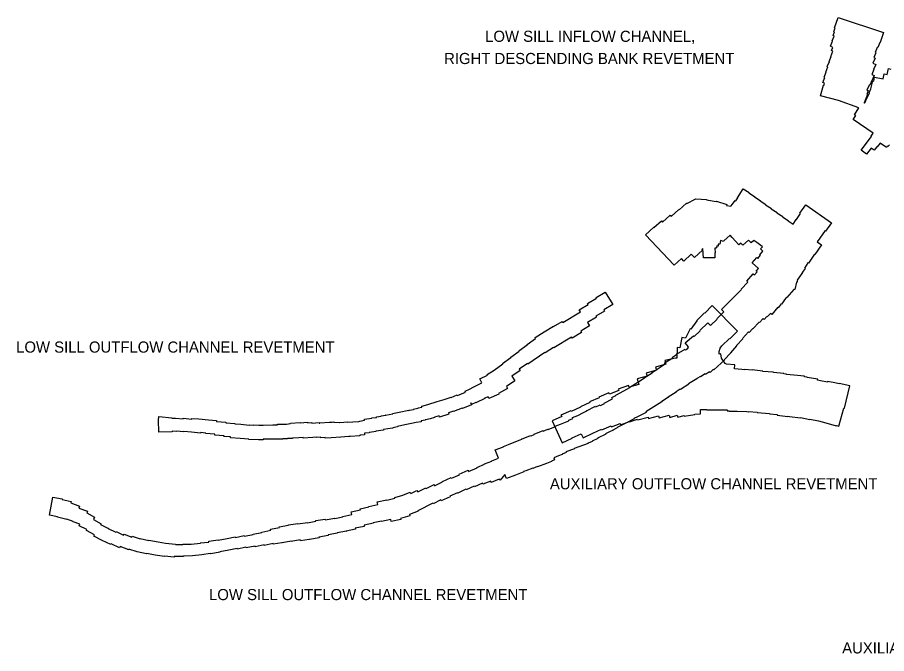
# Model space of a CAD drawing. Extents: x 2650582 to 3923188, y 277893 to 989177.
# Drawn here: x 3186396 to 3198891, y 930026 to 939166 of the extents above; entities that cross this region are included whole.
import ezdxf

# ---------------------------------------------------------------- set-up
doc = ezdxf.new("R2010")
doc.units = 0
doc.layers.add('Level 3', color=7, linetype='Continuous')

msp = doc.modelspace()

# ---------------------------------------------------------------- linework, layer by layer
at = {"layer": 'Level 3'}
for points in [[(3197941, 938040), (3197982, 938191), (3197989, 938189), (3198000, 938220), (3197972, 938232), (3198004, 938302), (3197994, 938306), (3198024, 938378), (3198017, 938381), (3198048, 938454), (3198038, 938459), (3198068, 938531), (3198065, 938532), (3198096, 938603), (3198088, 938606), (3198119, 938679), (3198098, 938690), (3198119, 938736), (3198083, 938752), (3198113, 938827), (3198106, 938830), (3198135, 938899), (3198122, 938905), (3198143, 938958), (3198133, 938962), (3198151, 939013), (3198143, 939016), (3198194, 939166), (3198848, 938951)], [(3198848, 938951), (3198799, 938806), (3198792, 938808), (3198763, 938733), (3198757, 938735), (3198726, 938663), (3198735, 938659), (3198707, 938590), (3198727, 938581), (3198695, 938508), (3198735, 938490), (3198704, 938420), (3198709, 938418), (3198678, 938348), (3198711, 938333), (3198648, 938191), (3198640, 938194), (3198607, 938123), (3198627, 938114), (3198606, 938060), (3198614, 938057), (3198566, 937938)], [(3198566, 937938), (3198574, 937933), (3198591, 937963), (3198587, 937965), (3198644, 938083), (3198642, 938084), (3198663, 938138), (3198691, 938254), (3198707, 938251), (3198719, 938307), (3198842, 938285), (3198856, 938355), (3198900, 938347), (3198918, 938430), (3198951, 938424)], [(3198410, 937700), (3198447, 937756), (3198428, 937768), (3198491, 937867), (3198201, 937972), (3197941, 938040)], [(3198525, 937257), (3198676, 937456), (3198669, 937461), (3198696, 937501), (3198410, 937700)], [(3198934, 937335), (3198907, 937311), (3198901, 937318), (3198889, 937299), (3198797, 937360), (3198757, 937305), (3198751, 937309), (3198714, 937257), (3198670, 937288), (3198603, 937199), (3198525, 937257)], [(3196678, 936485), (3196714, 936536), (3196725, 936529), (3196752, 936572), (3196746, 936576), (3196828, 936705), (3196914, 936650), (3196910, 936644), (3196993, 936591), (3196991, 936587), (3197074, 936534), (3197073, 936531), (3197156, 936478), (3197152, 936473), (3197235, 936420), (3197233, 936416), (3197316, 936363), (3197313, 936359), (3197397, 936306), (3197393, 936301), (3197476, 936248), (3197474, 936244), (3197547, 936196)], [(3195909, 936400), (3196013, 936495), (3196018, 936491), (3196148, 936560), (3196304, 936550), (3196304, 936545), (3196443, 936520), (3196446, 936527), (3196594, 936478), (3196589, 936463), (3196654, 936456), (3196678, 936485)], [(3196250, 935845), (3196235, 935831), (3196244, 935821), (3196131, 935715), (3196082, 935766), (3195975, 935666), (3195941, 935703), (3195836, 935607), (3195427, 936043), (3195544, 936151), (3195547, 936148), (3195653, 936244), (3195671, 936225), (3195781, 936324), (3195796, 936307), (3195903, 936406), (3195909, 936400)], [(3197547, 936196), (3197592, 936263), (3197595, 936262), (3197655, 936348), (3197644, 936355), (3197728, 936474), (3198098, 936216), (3198014, 936097), (3198006, 936103), (3197929, 935993), (3197929, 935994), (3197894, 935941), (3197955, 935899), (3197859, 935760), (3197854, 935763), (3197768, 935634), (3197758, 935640), (3197710, 935565), (3197719, 935559), (3197679, 935500), (3197680, 935499), (3197606, 935390), (3197608, 935389), (3197605, 935383), (3197604, 935364), (3197597, 935364), (3197574, 935255), (3197557, 935257), (3197456, 935143), (3197452, 935146)], [(3196982, 935962), (3196944, 935926), (3196905, 935968), (3196824, 935894), (3196797, 935924), (3196767, 935898), (3196673, 936006), (3196640, 936037), (3196553, 935954)], [(3196553, 935954), (3196550, 935958), (3196545, 935945), (3196502, 935960), (3196493, 935906), (3196471, 935909), (3196470, 935881), (3196452, 935882), (3196451, 935861), (3196442, 935861), (3196441, 935850), (3196423, 935851), (3196426, 935782), (3196423, 935782), (3196424, 935714), (3196257, 935712), (3196256, 935774), (3196254, 935774), (3196250, 935845)], [(3196959, 935638), (3197027, 935716), (3197041, 935704), (3197078, 935751), (3197070, 935757), (3197114, 935810), (3197080, 935839), (3197108, 935871), (3197104, 935874), (3197104, 935875), (3197024, 935931), (3197025, 935932), (3196982, 935962)], [(3196044, 934432), (3195996, 934489), (3196116, 934590), (3196123, 934583), (3196211, 934662), (3196207, 934667), (3196319, 934777), (3196357, 934739), (3196454, 934831), (3196449, 934836), (3196551, 934936), (3196519, 934970), (3196619, 935068), (3196805, 935259), (3196802, 935261), (3196894, 935363), (3196880, 935376), (3196972, 935483), (3196992, 935466), (3197030, 935511), (3197018, 935521), (3197051, 935559), (3196959, 935638)], [(3193844, 934554), (3193837, 934565), (3193967, 934649), (3193966, 934650), (3194101, 934729), (3194104, 934724), (3194229, 934795), (3194236, 934785), (3194491, 934935), (3194473, 934964), (3194601, 935041), (3194593, 935055), (3194719, 935131), (3194714, 935140), (3194846, 935220), (3194955, 935042), (3194827, 934966), (3194838, 934947), (3194711, 934874), (3194720, 934858), (3194593, 934781), (3194621, 934734), (3194494, 934657), (3194504, 934640), (3194371, 934559), (3194363, 934572), (3194105, 934420), (3194103, 934423), (3193982, 934345), (3193977, 934353), (3193733, 934185)], [(3197452, 935146), (3197436, 935129), (3197381, 935047), (3197374, 935052), (3197333, 934996), (3197325, 935002), (3197286, 934949), (3197282, 934952), (3197241, 934897), (3197220, 934913), (3197175, 934864), (3197169, 934870), (3197129, 934827), (3197118, 934838), (3197066, 934782), (3197059, 934789), (3196966, 934691), (3196963, 934694), (3196913, 934641), (3196906, 934647), (3196819, 934554), (3196823, 934550), (3196731, 934453), (3196735, 934449), (3196703, 934416), (3196706, 934413), (3196647, 934349), (3196651, 934345), (3196558, 934246), (3196561, 934243), (3196512, 934199), (3196514, 934197), (3196406, 934101), (3196400, 934108), (3196353, 934066), (3196345, 934075), (3196287, 934035), (3196281, 934043)], [(3196703, 934115), (3196708, 934173), (3196591, 934183), (3196570, 934196), (3196518, 934272), (3196506, 934334), (3196485, 934330), (3196486, 934365), (3196496, 934415), (3196522, 934449), (3196524, 934447), (3196633, 934552), (3196637, 934548), (3196747, 934660), (3196384, 935025), (3196278, 934918), (3196275, 934921), (3196162, 934810), (3196164, 934807), (3196076, 934686), (3196068, 934690), (3195999, 934556), (3195948, 934566), (3195918, 934421), (3195880, 934422), (3195874, 934272), (3195855, 934270), (3195854, 934272), (3195702, 934239), (3195715, 934182), (3195569, 934140), (3195582, 934098), (3195436, 934055), (3195449, 934013), (3195307, 933972), (3195329, 933891), (3195191, 933853), (3195182, 933879), (3195033, 933827), (3195041, 933805), (3194907, 933755), (3194898, 933773), (3194753, 933712), (3194758, 933701), (3194622, 933641), (3194625, 933635), (3194489, 933572), (3194491, 933568), (3194358, 933506), (3194353, 933516), (3194210, 933452), (3194221, 933430), (3194085, 933368)], [(3193073, 933914), (3193045, 933975), (3193155, 934025), (3193147, 934037), (3193251, 934100), (3193375, 934187), (3193369, 934195), (3193490, 934280), (3193487, 934284), (3193610, 934369), (3193604, 934378), (3193725, 934464), (3193722, 934468), (3193844, 934554)], [(3195871, 934326), (3195994, 934399), (3195998, 934391), (3196040, 934416), (3196034, 934423), (3196044, 934432)], [(3194998, 933740), (3195115, 933801), (3195114, 933803), (3195202, 933848), (3195200, 933852), (3195314, 933924), (3195313, 933925), (3195410, 933987), (3195408, 933990), (3195523, 934062), (3195521, 934065), (3195595, 934111), (3195593, 934114), (3195708, 934187), (3195699, 934203), (3195819, 934274), (3195811, 934287), (3195873, 934323), (3195871, 934326)], [(3193733, 934185), (3193727, 934194), (3193611, 934114), (3193623, 934094), (3193502, 934010), (3193545, 933946), (3193426, 933863), (3193440, 933837), (3193312, 933765), (3193317, 933754), (3193175, 933689), (3193162, 933717)], [(3196281, 934043), (3196216, 934004), (3196214, 934007), (3196162, 933977), (3196164, 933974), (3196045, 933903), (3196049, 933895), (3195926, 933822), (3195925, 933824), (3195866, 933786), (3195868, 933783), (3195753, 933710), (3195755, 933708), (3195658, 933647), (3195660, 933644), (3195546, 933572), (3195547, 933570), (3195432, 933498), (3195435, 933492), (3195308, 933427), (3195308, 933427), (3195259, 933402), (3195261, 933398)], [(3197114, 934084), (3196959, 934101), (3196958, 934096), (3196847, 934106), (3196847, 934104), (3196808, 934107), (3196808, 934106), (3196703, 934115)], [(3198360, 933871), (3198208, 933905), (3198208, 933904), (3198191, 933908), (3198191, 933906), (3198121, 933920), (3198043, 933937), (3198040, 933927), (3197940, 933946), (3197940, 933945), (3197899, 933953), (3197901, 933970), (3197750, 933993), (3197750, 933999), (3197712, 934003), (3197713, 934010), (3197558, 934028), (3197558, 934025), (3197450, 934036), (3197450, 934041), (3197413, 934044), (3197413, 934049), (3197263, 934063), (3197263, 934067), (3197114, 934081), (3197114, 934084)], [(3192296, 933603), (3192296, 933606), (3192429, 933649), (3192430, 933646), (3192531, 933678), (3192531, 933676), (3192633, 933709), (3192633, 933707), (3192720, 933742), (3192722, 933736), (3192839, 933783), (3192833, 933795), (3192896, 933825), (3192895, 933827), (3192959, 933857), (3192958, 933860), (3193073, 933914)], [(3198274, 933554), (3198286, 933551), (3198360, 933871)], [(3193162, 933717), (3193112, 933694), (3193114, 933690), (3192986, 933630), (3192985, 933633), (3192924, 933603), (3192912, 933629), (3192924, 933601), (3192794, 933548), (3192791, 933554), (3192665, 933503), (3192663, 933508), (3192592, 933485), (3192599, 933465), (3192465, 933422), (3192459, 933443), (3192392, 933422), (3192394, 933417), (3192329, 933401), (3192330, 933398), (3192261, 933385), (3192259, 933384), (3192260, 933380), (3192198, 933368), (3192200, 933358), (3192129, 933347), (3192130, 933344), (3192061, 933334), (3192062, 933331), (3191965, 933312), (3191965, 933312), (3191859, 933291), (3191860, 933283), (3191791, 933271), (3191791, 933267), (3191722, 933257), (3191723, 933253), (3191658, 933244), (3191659, 933237)], [(3193311, 932834), (3193265, 932952), (3193385, 932998), (3193384, 932999), (3193458, 933028), (3193457, 933032), (3193587, 933083), (3193587, 933082), (3193623, 933096), (3193645, 933105), (3193644, 933107), (3193773, 933157), (3193775, 933152), (3193783, 933155), (3193783, 933156), (3193825, 933172), (3193823, 933178), (3193952, 933229), (3193954, 933224), (3194023, 933251), (3194025, 933246), (3194130, 933287), (3194128, 933292), (3194204, 933320), (3194202, 933324), (3194325, 933370), (3194321, 933380), (3194382, 933403), (3194376, 933417), (3194454, 933447), (3194534, 933488), (3194532, 933490), (3194580, 933514), (3194579, 933516), (3194705, 933581), (3194712, 933569), (3194771, 933599), (3194776, 933589), (3194835, 933619), (3194833, 933623), (3194952, 933685), (3194941, 933706), (3195000, 933736), (3194998, 933740)], [(3191624, 933441), (3191690, 933450), (3191689, 933452), (3191791, 933469), (3191790, 933477), (3191886, 933496), (3192024, 933523), (3192025, 933520), (3192033, 933521), (3192033, 933525), (3192088, 933533), (3192087, 933540), (3192158, 933553), (3192157, 933558), (3192212, 933568), (3192209, 933582), (3192296, 933603)], [(3194085, 933368), (3194228, 933056), (3194371, 933123), (3194370, 933125), (3194501, 933185), (3194529, 933126), (3194670, 933191), (3194668, 933195), (3194794, 933252), (3194799, 933240), (3194930, 933296), (3194935, 933282), (3195060, 933331), (3195068, 933312), (3195193, 933359), (3195195, 933355), (3195311, 933395), (3195315, 933383), (3195461, 933423), (3195466, 933403), (3195611, 933442), (3195620, 933411), (3195765, 933453), (3195775, 933420), (3195882, 933450), (3195888, 933425), (3195979, 933445), (3195980, 933439), (3196134, 933462), (3196134, 933465), (3196218, 933471), (3196214, 933532)], [(3196214, 933532), (3196307, 933532), (3196307, 933529), (3196334, 933529), (3196334, 933526), (3196483, 933528), (3196484, 933526), (3196598, 933526), (3196598, 933515), (3196627, 933514), (3196627, 933509), (3196741, 933508), (3196741, 933508), (3196882, 933502), (3196882, 933503), (3196910, 933501), (3196910, 933505), (3197028, 933496)], [(3197028, 933496), (3197028, 933489), (3197206, 933474), (3197206, 933472), (3197316, 933460), (3197316, 933453), (3197471, 933434), (3197471, 933438), (3197497, 933434), (3197651, 933412), (3197651, 933416), (3197788, 933391), (3197788, 933395), (3197910, 933369), (3198017, 933342), (3198016, 933340), (3198167, 933298), (3198169, 933304), (3198202, 933295), (3198274, 933554)], [(3190210, 933108), (3190073, 933107), (3190073, 933106), (3190004, 933105), (3190004, 933105), (3189930, 933105), (3189929, 933095), (3189862, 933097), (3189862, 933096), (3189721, 933101), (3189721, 933105), (3189598, 933116), (3189598, 933115), (3189459, 933128), (3189460, 933138), (3189366, 933146), (3189367, 933153), (3189235, 933164), (3189236, 933178), (3189102, 933189), (3189103, 933195), (3189028, 933201), (3189028, 933195), (3188900, 933206), (3188900, 933205), (3188791, 933215), (3188791, 933213), (3188685, 933223), (3188685, 933217), (3188623, 933220), (3188623, 933210), (3188427, 933205), (3188423, 933379), (3188426, 933379), (3188431, 933434), (3188617, 933415), (3188616, 933410), (3188668, 933408), (3188668, 933409), (3188777, 933400), (3188777, 933407), (3188905, 933396), (3188905, 933405), (3189002, 933397), (3189002, 933399), (3189141, 933386), (3189141, 933383), (3189259, 933373), (3189258, 933362), (3189392, 933350), (3189391, 933343), (3189523, 933332), (3189522, 933327), (3189607, 933320), (3189607, 933320), (3189728, 933309), (3189728, 933311), (3189796, 933309), (3189796, 933311), (3189865, 933308), (3189931, 933308), (3189931, 933310), (3190069, 933311), (3190069, 933315), (3190137, 933315)], [(3190137, 933315), (3190137, 933320), (3190264, 933321), (3190321, 933332), (3190321, 933337), (3190461, 933348), (3190462, 933343), (3190565, 933351), (3190565, 933342), (3190628, 933347), (3190629, 933336), (3190732, 933344), (3190733, 933337), (3190743, 933338), (3190743, 933340), (3190884, 933351), (3190884, 933349), (3190919, 933351), (3190946, 933354), (3190946, 933350), (3191025, 933346), (3191031, 933346), (3191031, 933346), (3191144, 933354), (3191144, 933352), (3191219, 933358), (3191219, 933356), (3191303, 933362), (3191303, 933362), (3191317, 933363), (3191386, 933382), (3191385, 933392), (3191493, 933407), (3191492, 933411), (3191557, 933420), (3191556, 933427), (3191625, 933436), (3191624, 933441)], [(3195261, 933398), (3195134, 933332), (3195133, 933334), (3195017, 933274), (3195019, 933270), (3194957, 933238), (3194958, 933237), (3194898, 933207), (3194899, 933206), (3194852, 933182), (3194853, 933180), (3194737, 933120), (3194738, 933118), (3194658, 933077), (3194659, 933073), (3194626, 933060), (3194611, 933053), (3194611, 933054), (3194598, 933050), (3194600, 933045), (3194467, 932995), (3194466, 932998), (3194401, 932973), (3194403, 932970), (3194281, 932923), (3194284, 932915), (3194227, 932892), (3194229, 932888), (3194173, 932866), (3194174, 932865), (3194105, 932838), (3194116, 932809), (3194073, 932793)], [(3191659, 933237), (3191551, 933222), (3191552, 933218), (3191452, 933204), (3191453, 933197), (3191384, 933192), (3191386, 933167), (3191318, 933162), (3191319, 933155), (3191179, 933144), (3191178, 933146), (3191160, 933145), (3191160, 933144), (3191047, 933136), (3191047, 933135), (3190906, 933124), (3190906, 933128), (3190822, 933122), (3190821, 933133), (3190759, 933128), (3190759, 933134), (3190691, 933129), (3190691, 933137), (3190644, 933133), (3190644, 933133), (3190504, 933122), (3190503, 933131), (3190441, 933126), (3190441, 933128), (3190350, 933121), (3190350, 933114), (3190278, 933114), (3190278, 933111), (3190210, 933111), (3190210, 933108)], [(3191824, 932258), (3191820, 932269), (3191937, 932301), (3192044, 932343), (3192052, 932324), (3192138, 932368), (3192150, 932348), (3192266, 932409), (3192272, 932398), (3192386, 932454), (3192394, 932438), (3192506, 932494), (3192505, 932497), (3192632, 932555), (3192637, 932544), (3192752, 932595), (3192748, 932603), (3192874, 932660), (3192881, 932644), (3193004, 932695), (3193001, 932702), (3193113, 932746), (3193111, 932752), (3193215, 932792), (3193214, 932796), (3193311, 932834)], [(3194073, 932793), (3194076, 932787), (3194003, 932758), (3194003, 932757), (3193874, 932707), (3193872, 932712), (3193807, 932687), (3193805, 932692), (3193704, 932653), (3193704, 932654), (3193673, 932642), (3193675, 932638), (3193556, 932591), (3193556, 932591), (3193426, 932540), (3193402, 932601)], [(3193402, 932601), (3193335, 932519), (3193321, 932530), (3193206, 932486), (3193200, 932503), (3193089, 932462), (3193084, 932473), (3192968, 932423), (3192963, 932433), (3192847, 932380), (3192843, 932388), (3192725, 932333), (3192723, 932335), (3192612, 932286), (3192615, 932278), (3192486, 932221), (3192481, 932234), (3192371, 932177), (3192367, 932187), (3192153, 932077), (3192155, 932073), (3192032, 932022), (3192036, 932005), (3191903, 931967), (3191906, 931952), (3191769, 931922)], [(3188509, 931420), (3188376, 931442), (3188376, 931442), (3188255, 931464), (3188254, 931458), (3188118, 931486), (3188119, 931488), (3188000, 931526), (3187996, 931517), (3187873, 931563), (3187864, 931545), (3187744, 931601), (3187741, 931594), (3187616, 931653), (3187496, 931714), (3187505, 931732), (3187389, 931793), (3187396, 931807), (3187285, 931861), (3187296, 931884), (3187196, 931919), (3187198, 931924), (3187108, 931959), (3187107, 931954), (3186972, 931984), (3186974, 931993), (3186857, 932014), (3186904, 932274), (3187042, 932248), (3187041, 932239), (3187167, 932210), (3187164, 932191), (3187288, 932142), (3187279, 932117), (3187402, 932073), (3187393, 932046), (3187506, 931988), (3187488, 931952), (3187598, 931892), (3187593, 931880), (3187704, 931825), (3187702, 931822), (3187811, 931771), (3187815, 931778), (3187923, 931729), (3187929, 931744), (3188042, 931700), (3188046, 931711), (3188159, 931677), (3188159, 931679), (3188285, 931653), (3188285, 931656), (3188418, 931632), (3188418, 931632), (3188526, 931614)], [(3190162, 931839), (3190160, 931849), (3190293, 931872), (3190292, 931875), (3190428, 931897), (3190429, 931891), (3190564, 931911), (3190564, 931907), (3190686, 931928), (3190685, 931936), (3190821, 931959), (3190823, 931947), (3190956, 931972), (3190957, 931967), (3191074, 931992), (3191073, 931998), (3191205, 932024), (3191196, 932061), (3191326, 932090), (3191322, 932106), (3191449, 932135), (3191448, 932140), (3191576, 932170), (3191568, 932207), (3191705, 932237), (3191706, 932232), (3191824, 932258)], [(3191769, 931922), (3191762, 931954), (3191631, 931924), (3191630, 931930), (3191512, 931903), (3191513, 931900), (3191380, 931869), (3191383, 931853), (3191253, 931827), (3191255, 931815), (3191124, 931787), (3191125, 931786), (3190995, 931761), (3190996, 931756), (3190863, 931731), (3190865, 931723), (3190731, 931697), (3190732, 931689), (3190593, 931663), (3190592, 931666), (3190464, 931645), (3190461, 931661), (3190330, 931638), (3190330, 931639), (3190200, 931615), (3190199, 931619), (3190075, 931597)], [(3188526, 931614), (3188669, 931600), (3188668, 931591), (3188773, 931591), (3188773, 931596), (3188894, 931599), (3189026, 931612), (3189025, 931616), (3189149, 931627), (3189147, 931641), (3189283, 931660), (3189284, 931656), (3189410, 931680), (3189411, 931678), (3189527, 931705), (3189529, 931694), (3189657, 931724), (3189660, 931714), (3189783, 931739), (3189783, 931742), (3189909, 931767), (3189908, 931770), (3190037, 931797), (3190034, 931813), (3190162, 931839)], [(3190075, 931597), (3190073, 931606), (3189944, 931578), (3189942, 931587), (3189815, 931561), (3189812, 931569), (3189684, 931544), (3189681, 931556), (3189558, 931526), (3189555, 931537), (3189435, 931510), (3189435, 931511), (3189308, 931487), (3189309, 931481), (3189170, 931457), (3189169, 931462), (3189046, 931446), (3189046, 931443), (3188911, 931430), (3188783, 931425), (3188783, 931419), (3188651, 931419), (3188649, 931413), (3188510, 931427), (3188509, 931420)]]:
    msp.add_lwpolyline(points, dxfattribs=at)

# ---------------------------------------------------------------- texts
for s, p in [('LOW SILL INFLOW CHANNEL,', (3193120, 938815)), ('RIGHT DESCENDING BANK REVETMENT', (3192530, 938496)), ('LOW SILL OUTFLOW CHANNEL REVETMENT', (3186378, 934350)), ('AUXILIARY OUTFLOW CHANNEL REVETMENT', (3194051, 932386)), ('LOW SILL OUTFLOW CHANNEL REVETMENT', (3189151, 930794)), ('AUXILIARY INFLOW CHANNEL REVETMENT', (3198252, 930028))]:
    msp.add_text(s, height=160, dxfattribs=at).set_placement(p)

doc.saveas('drawing.dxf')
